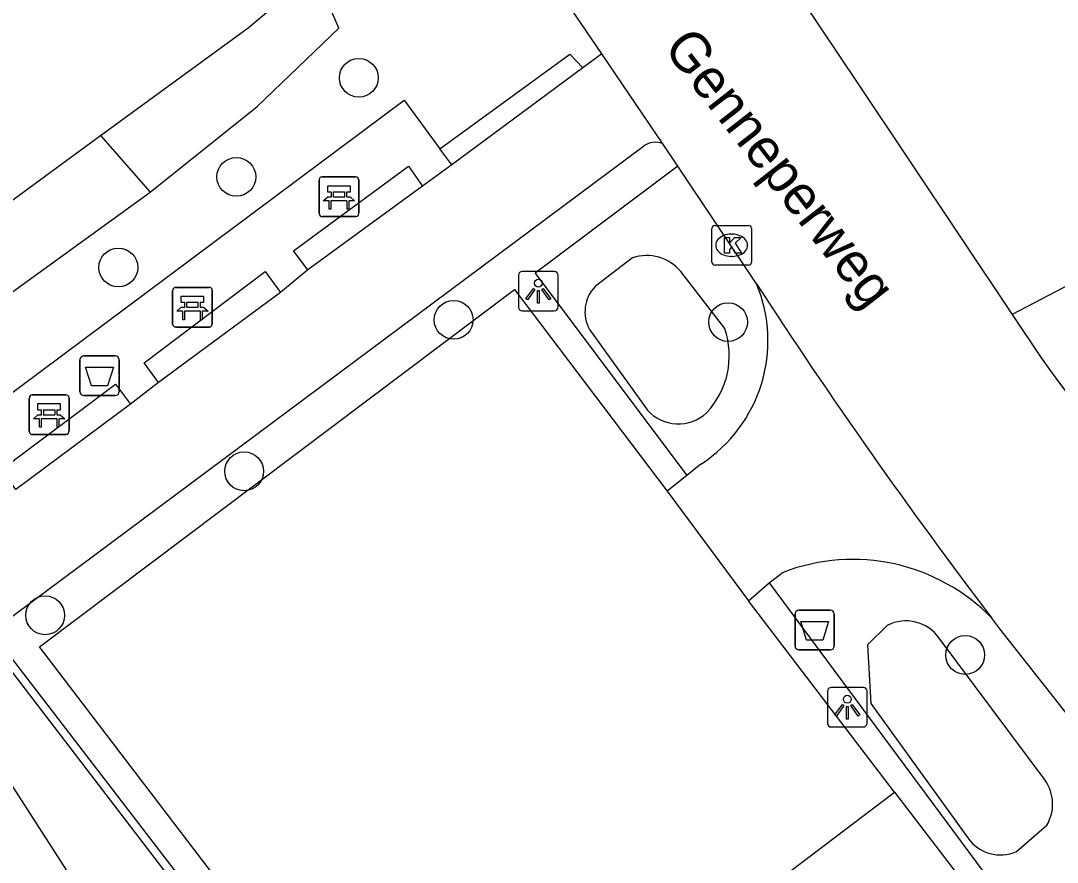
# Model space of a CAD drawing. Extents: x 160203 to 161526, y 379529 to 381797.
# Drawn here: x 160758.29 to 160784.41, y 381511.28 to 381532.5 of the extents above; entities that cross this region are included whole.
import ezdxf

# ---------------------------------------------------------------- set-up
doc = ezdxf.new("R2010")
doc.units = 0
for name, color, linetype in [('IMGEO_Afvalbak', 7, 'Continuous'), ('IMGEO_Bank', 7, 'Continuous'), ('IMGEO_Boom', 7, 'Continuous'), ('IMGEO_Groenvoorziening', 7, 'Continuous'), ('IMGEO_Haag', 7, 'Continuous'), ('IMGEO_Kolk', 7, 'Continuous'), ('IMGEO_Lichtpunt', 7, 'Continuous'), ('IMGEO_Oever', 7, 'Continuous'), ('IMGEO_Openbare_ruimte_label', 7, 'Continuous'), ('IMGEO_Parkeervlak_halfverhard', 7, 'Continuous'), ('IMGEO_Rijbaan_lokaal_gesloten', 7, 'Continuous'), ('IMGEO_Rijbaan_lokaal_open', 7, 'Continuous'), ('IMGEO_Voetpad_open', 7, 'Continuous'), ('IMGEO_Waterloop', 7, 'Continuous')]:
    doc.layers.add(name, color=color, linetype=linetype)

msp = doc.modelspace()

# ---------------------------------------------------------------- linework, layer by layer
at = {"layer": 'IMGEO_Afvalbak'}
for p, q in [((160759.78, 381523.147), (160759.78, 381523.947)), ((160759.78, 381523.947), (160759.78, 381523.147)), ((160759.88, 381524.047), (160760.67, 381524.047)), ((160760.67, 381524.047), (160759.88, 381524.047)), ((160760.77, 381523.947), (160760.77, 381523.147)), ((160760.77, 381523.147), (160760.77, 381523.947)), ((160760.67, 381523.047), (160759.88, 381523.047)), ((160759.88, 381523.047), (160760.67, 381523.047)), ((160777.798, 381516.733), (160777.798, 381517.533)), ((160777.798, 381517.533), (160777.798, 381516.733)), ((160777.898, 381517.633), (160778.688, 381517.633)), ((160778.688, 381517.633), (160777.898, 381517.633)), ((160778.788, 381517.533), (160778.788, 381516.733)), ((160778.788, 381516.733), (160778.788, 381517.533)), ((160778.688, 381516.633), (160777.898, 381516.633)), ((160777.898, 381516.633), (160778.688, 381516.633))]:
    msp.add_line(p, q, dxfattribs=at)
for points in [[(160759.923, 381523.761), (160760.627, 381523.761), (160760.478, 381523.291), (160760.072, 381523.291), (160759.923, 381523.761)], [(160777.941, 381517.347), (160778.645, 381517.347), (160778.496, 381516.877), (160778.09, 381516.877), (160777.941, 381517.347)]]:
    msp.add_lwpolyline(points, dxfattribs=at)
for centre, start, end in [((160759.88, 381523.947), 90, 180), ((160759.88, 381523.947), 90, 180), ((160760.67, 381523.947), 0, 90), ((160760.67, 381523.947), 360, 90), ((160759.88, 381523.147), 180, 270), ((160759.88, 381523.147), 180, 270), ((160760.67, 381523.147), 270, 0), ((160760.67, 381523.147), 270, 0), ((160777.898, 381517.533), 90, 180), ((160777.898, 381517.533), 90, 180), ((160778.688, 381517.533), 0, 90), ((160778.688, 381517.533), 360, 90), ((160777.898, 381516.733), 180, 270), ((160777.898, 381516.733), 180, 270), ((160778.688, 381516.733), 270, 0), ((160778.688, 381516.733), 270, 0)]:
    msp.add_arc(centre, 0.1, start, end, dxfattribs=at)
at = {"layer": 'IMGEO_Bank'}
for p, q in [((160765.806, 381527.634), (160765.806, 381528.475)), ((160765.806, 381528.475), (160765.806, 381527.634)), ((160765.881, 381528.559), (160766.722, 381528.559)), ((160766.722, 381528.559), (160765.881, 381528.559)), ((160766.806, 381528.484), (160766.806, 381527.643)), ((160766.806, 381527.643), (160766.806, 381528.484)), ((160766.115, 381528.065), (160766.115, 381528.171)), ((160766.159, 381528.171), (160766.159, 381528.065)), ((160766.447, 381528.177), (160766.165, 381528.177)), ((160766.453, 381528.065), (160766.453, 381528.171)), ((160766.497, 381528.171), (160766.497, 381528.065)), ((160766.503, 381527.957), (160766.11, 381527.957)), ((160766.165, 381528.059), (160766.447, 381528.059)), ((160766.731, 381527.559), (160765.89, 381527.559)), ((160765.89, 381527.559), (160766.731, 381527.559)), ((160762.19, 381525.775), (160763.031, 381525.775)), ((160763.031, 381525.775), (160762.19, 381525.775)), ((160762.115, 381524.85), (160762.115, 381525.691)), ((160762.115, 381525.691), (160762.115, 381524.85)), ((160763.115, 381525.7), (160763.115, 381524.859)), ((160763.115, 381524.859), (160763.115, 381525.7)), ((160762.424, 381525.281), (160762.424, 381525.387)), ((160762.468, 381525.387), (160762.468, 381525.281)), ((160762.756, 381525.393), (160762.474, 381525.393)), ((160762.474, 381525.275), (160762.756, 381525.275)), ((160762.762, 381525.281), (160762.762, 381525.387)), ((160762.806, 381525.387), (160762.806, 381525.281)), ((160762.812, 381525.173), (160762.419, 381525.173)), ((160763.04, 381524.775), (160762.199, 381524.775)), ((160762.199, 381524.775), (160763.04, 381524.775)), ((160758.504, 381522.139), (160758.504, 381522.98)), ((160758.504, 381522.98), (160758.504, 381522.139)), ((160758.579, 381523.064), (160759.42, 381523.064)), ((160759.42, 381523.064), (160758.579, 381523.064)), ((160759.504, 381522.989), (160759.504, 381522.148)), ((160759.504, 381522.148), (160759.504, 381522.989)), ((160758.813, 381522.57), (160758.813, 381522.676)), ((160758.857, 381522.676), (160758.857, 381522.57)), ((160759.145, 381522.682), (160758.863, 381522.682)), ((160759.151, 381522.57), (160759.151, 381522.676)), ((160759.195, 381522.676), (160759.195, 381522.57)), ((160759.201, 381522.462), (160758.808, 381522.462)), ((160758.863, 381522.564), (160759.145, 381522.564)), ((160759.429, 381522.064), (160758.588, 381522.064)), ((160758.588, 381522.064), (160759.429, 381522.064))]:
    msp.add_line(p, q, dxfattribs=at)
for points in [[(160766.109, 381528.177), (160766.023, 381528.177), (160766.023, 381528.338), (160766.586, 381528.338), (160766.586, 381528.177), (160766.503, 381528.177)], [(160766.053, 381527.957), (160765.911, 381527.957), (160766.023, 381528.059), (160766.109, 381528.059)], [(160766.103, 381527.95), (160766.103, 381527.743), (160766.06, 381527.743), (160766.06, 381527.95)], [(160766.503, 381528.059), (160766.586, 381528.059), (160766.698, 381527.957), (160766.559, 381527.957)], [(160766.553, 381527.95), (160766.553, 381527.743), (160766.509, 381527.743), (160766.509, 381527.95)], [(160762.418, 381525.393), (160762.332, 381525.393), (160762.332, 381525.554), (160762.895, 381525.554), (160762.895, 381525.393), (160762.812, 381525.393)], [(160762.362, 381525.173), (160762.22, 381525.173), (160762.332, 381525.275), (160762.418, 381525.275)], [(160762.812, 381525.275), (160762.895, 381525.275), (160763.007, 381525.173), (160762.868, 381525.173)], [(160762.412, 381525.166), (160762.412, 381524.959), (160762.369, 381524.959), (160762.369, 381525.166)], [(160762.862, 381525.166), (160762.862, 381524.959), (160762.818, 381524.959), (160762.818, 381525.166)], [(160758.807, 381522.682), (160758.721, 381522.682), (160758.721, 381522.843), (160759.284, 381522.843), (160759.284, 381522.682), (160759.201, 381522.682)], [(160758.751, 381522.462), (160758.609, 381522.462), (160758.721, 381522.564), (160758.807, 381522.564)], [(160758.801, 381522.455), (160758.801, 381522.248), (160758.758, 381522.248), (160758.758, 381522.455)], [(160759.201, 381522.564), (160759.284, 381522.564), (160759.396, 381522.462), (160759.257, 381522.462)], [(160759.251, 381522.455), (160759.251, 381522.248), (160759.207, 381522.248), (160759.207, 381522.455)]]:
    msp.add_lwpolyline(points, dxfattribs=at)
for centre, radius, start, end in [((160765.884, 381528.481), 0.0779, 92.4484, 184.2845), ((160765.884, 381528.481), 0.0779, 92.4484, 184.2845), ((160766.728, 381528.481), 0.0779, 2.4484, 94.2845), ((160766.728, 381528.481), 0.0779, 2.4484, 94.2845), ((160766.108, 381528.17), 0.00671, 2.8957, 87.1043), ((160766.165, 381528.17), 0.00671, 92.8957, 177.1043), ((160766.447, 381528.17), 0.00671, 2.8957, 87.1043), ((160766.504, 381528.17), 0.00671, 92.8957, 177.1043), ((160766.053, 381527.95), 0.00671, 2.8957, 87.1043), ((160766.11, 381527.95), 0.00671, 92.8957, 177.1043), ((160766.108, 381528.066), 0.00671, 272.8957, 357.1043), ((160766.165, 381528.066), 0.00671, 182.8957, 267.1043), ((160766.447, 381528.066), 0.00671, 272.8957, 357.1043), ((160766.504, 381528.066), 0.00671, 182.8957, 267.1043), ((160766.502, 381527.95), 0.00671, 2.8957, 87.1043), ((160766.559, 381527.95), 0.00671, 92.8957, 177.1043), ((160765.884, 381527.637), 0.0779, 182.4484, 274.2845), ((160765.884, 381527.637), 0.0779, 182.4484, 274.2845), ((160766.728, 381527.637), 0.0779, 272.4484, 4.2845), ((160766.728, 381527.637), 0.0779, 272.4484, 4.2845), ((160762.193, 381525.697), 0.0779, 92.4484, 184.2845), ((160762.193, 381525.697), 0.0779, 92.4484, 184.2845), ((160763.037, 381525.697), 0.0779, 2.4484, 94.2845), ((160763.037, 381525.697), 0.0779, 2.4484, 94.2845), ((160762.417, 381525.386), 0.00671, 2.8957, 87.1043), ((160762.417, 381525.282), 0.00671, 272.8957, 357.1043), ((160762.474, 381525.386), 0.00671, 92.8957, 177.1043), ((160762.474, 381525.282), 0.00671, 182.8957, 267.1043), ((160762.756, 381525.386), 0.00671, 2.8957, 87.1043), ((160762.756, 381525.282), 0.00671, 272.8957, 357.1043), ((160762.813, 381525.386), 0.00671, 92.8957, 177.1043), ((160762.813, 381525.282), 0.00671, 182.8957, 267.1043), ((160762.362, 381525.166), 0.00671, 2.8957, 87.1043), ((160762.419, 381525.166), 0.00671, 92.8957, 177.1043), ((160762.811, 381525.166), 0.00671, 2.8957, 87.1043), ((160762.868, 381525.166), 0.00671, 92.8957, 177.1043), ((160762.193, 381524.853), 0.0779, 182.4484, 274.2845), ((160762.193, 381524.853), 0.0779, 182.4484, 274.2845), ((160763.037, 381524.853), 0.0779, 272.4484, 4.2845), ((160763.037, 381524.853), 0.0779, 272.4484, 4.2845), ((160758.582, 381522.986), 0.0779, 92.4484, 184.2845), ((160758.582, 381522.986), 0.0779, 92.4484, 184.2845), ((160759.426, 381522.986), 0.0779, 2.4484, 94.2845), ((160759.426, 381522.986), 0.0779, 2.4484, 94.2845), ((160758.806, 381522.675), 0.00671, 2.8957, 87.1043), ((160758.863, 381522.675), 0.00671, 92.8957, 177.1043), ((160759.145, 381522.675), 0.00671, 2.8957, 87.1043), ((160759.202, 381522.675), 0.00671, 92.8957, 177.1043), ((160758.751, 381522.455), 0.00671, 2.8957, 87.1043), ((160758.808, 381522.455), 0.00671, 92.8957, 177.1043), ((160758.806, 381522.571), 0.00671, 272.8957, 357.1043), ((160758.863, 381522.571), 0.00671, 182.8957, 267.1043), ((160759.145, 381522.571), 0.00671, 272.8957, 357.1043), ((160759.202, 381522.571), 0.00671, 182.8957, 267.1043), ((160759.2, 381522.455), 0.00671, 2.8957, 87.1043), ((160759.257, 381522.455), 0.00671, 92.8957, 177.1043), ((160758.582, 381522.142), 0.0779, 182.4484, 274.2845), ((160758.582, 381522.142), 0.0779, 182.4484, 274.2845), ((160759.426, 381522.142), 0.0779, 272.4484, 4.2845), ((160759.426, 381522.142), 0.0779, 272.4484, 4.2845)]:
    msp.add_arc(centre, radius, start, end, dxfattribs=at)
at = {"layer": 'IMGEO_Boom'}
for centre in [(160766.806, 381531.059), (160763.72, 381528.56), (160760.747, 381526.276), (160769.196, 381524.955), (160776.112, 381524.899), (160763.917, 381521.136), (160758.903, 381517.506), (160782.087, 381516.505)]:
    msp.add_circle(centre, 0.489, dxfattribs=at)
at = {"layer": 'IMGEO_Groenvoorziening'}
for points in [[(160761.545, 381528.175), (160764.244, 381530.339), (160766.301, 381532.313), (160766.102, 381532.781), (160765.423, 381533.506)], [(160748.707, 381518.45), (160751.828, 381521.043), (160754.07, 381522.473), (160756.183, 381524.294), (160761.545, 381528.175)]]:
    msp.add_lwpolyline(points, dxfattribs=at)
at = {"layer": 'IMGEO_Haag'}
for points in [[(160768.851, 381529.264), (160772.126, 381531.655), (160772.455, 381531.312)], [(160774.849, 381528.832), (160771.25, 381526.13), (160775.076, 381521.03)], [(160777.151, 381518.322), (160782.542, 381511.048)], [(160755.271, 381515.391), (160755.672, 381514.811), (160757.992, 381516.503), (160773.641, 381496.114), (160778, 381491.284)], [(160780.301, 381513.047), (160782.089, 381510.714), (160782.542, 381511.048)]]:
    msp.add_lwpolyline(points, dxfattribs=at)
at = {"layer": 'IMGEO_Kolk'}
for p, q in [((160775.777, 381527.336), (160776.629, 381527.336)), ((160775.702, 381526.41), (160775.702, 381527.262)), ((160776.19, 381527.116), (160776.215, 381527.116)), ((160776.703, 381527.262), (160776.703, 381526.41)), ((160776.213, 381526.556), (160776.188, 381526.556)), ((160776.629, 381526.336), (160775.777, 381526.336))]:
    msp.add_line(p, q, dxfattribs=at)
for points in [[(160775.777, 381527.336), (160776.629, 381527.336)], [(160775.702, 381526.41), (160775.702, 381527.262)], [(160776.703, 381527.262), (160776.703, 381526.41)], [(160776.023, 381527.036), (160776.146, 381527.036), (160776.146, 381526.885), (160776.276, 381527.036), (160776.44, 381527.036), (160776.294, 381526.885), (160776.447, 381526.636), (160776.295, 381526.636), (160776.21, 381526.8), (160776.146, 381526.733), (160776.146, 381526.636), (160776.023, 381526.636), (160776.023, 381527.036)], [(160776.629, 381526.336), (160775.777, 381526.336)]]:
    msp.add_lwpolyline(points, dxfattribs=at)
for centre, start, end in [((160775.779, 381527.26), 91.552, 178.448), ((160775.779, 381527.26), 91.552, 178.448), ((160776.627, 381527.26), 1.552, 88.448), ((160776.627, 381527.26), 1.552, 88.448), ((160775.779, 381526.412), 181.552, 268.448), ((160775.779, 381526.412), 181.552, 268.448), ((160776.627, 381526.412), 271.552, 358.448), ((160776.627, 381526.412), 271.552, 358.448)]:
    msp.add_arc(centre, 0.0765, start, end, dxfattribs=at)
for centre, major_axis, ratio, start_param, end_param in [((160776.189, 381526.836), (-0.387, 0.002), 0.722429, 4.712389, 7.853982), ((160776.214, 381526.836), (-0.39, 0.002), 0.717154, 1.570796, 4.712389)]:
    msp.add_ellipse(centre, major_axis=major_axis, ratio=ratio, start_param=start_param, end_param=end_param, dxfattribs=at)
at = {"layer": 'IMGEO_Lichtpunt'}
for p, q in [((160770.831, 381526.083), (160770.831, 381525.276)), ((160770.831, 381526.083), (160770.831, 381525.276)), ((160771.733, 381526.178), (160770.925, 381526.178)), ((160771.733, 381526.178), (160770.925, 381526.178)), ((160771.827, 381525.276), (160771.827, 381526.083)), ((160771.827, 381525.276), (160771.827, 381526.083)), ((160770.925, 381525.182), (160771.733, 381525.182)), ((160770.925, 381525.182), (160771.733, 381525.182)), ((160778.618, 381515.591), (160778.618, 381514.784)), ((160778.618, 381515.591), (160778.618, 381514.784)), ((160779.52, 381515.686), (160778.712, 381515.686)), ((160779.52, 381515.686), (160778.712, 381515.686)), ((160779.614, 381514.784), (160779.614, 381515.591)), ((160779.614, 381514.784), (160779.614, 381515.591)), ((160778.712, 381514.69), (160779.52, 381514.69)), ((160778.712, 381514.69), (160779.52, 381514.69))]:
    msp.add_line(p, q, dxfattribs=at)
for points in [[(160771.205, 381525.747), (160771.244, 381525.719), (160771.056, 381525.457), (160771.018, 381525.484), (160771.205, 381525.747)], [(160771.307, 381525.699), (160771.354, 381525.699), (160771.354, 381525.377), (160771.307, 381525.377), (160771.307, 381525.699)], [(160771.417, 381525.719), (160771.455, 381525.746), (160771.642, 381525.484), (160771.603, 381525.456), (160771.417, 381525.719)], [(160778.992, 381515.255), (160779.031, 381515.227), (160778.843, 381514.965), (160778.805, 381514.992), (160778.992, 381515.255)], [(160779.094, 381515.207), (160779.141, 381515.207), (160779.141, 381514.885), (160779.094, 381514.885), (160779.094, 381515.207)], [(160779.204, 381515.227), (160779.242, 381515.254), (160779.429, 381514.992), (160779.39, 381514.964), (160779.204, 381515.227)]]:
    msp.add_lwpolyline(points, dxfattribs=at)
for centre in [(160771.33, 381525.881), (160779.117, 381515.389)]:
    msp.add_circle(centre, 0.0994, dxfattribs=at)
for centre, start, end in [((160770.925, 381526.083), 90, 180), ((160770.925, 381526.083), 90, 180), ((160771.733, 381526.083), 0, 90), ((160771.733, 381526.083), 0, 90), ((160770.925, 381525.276), 180, 270), ((160770.925, 381525.276), 180, 270), ((160771.733, 381525.276), 270, 0), ((160771.733, 381525.276), 270, 360), ((160778.712, 381515.591), 90, 180), ((160778.712, 381515.591), 90, 180), ((160779.52, 381515.591), 0, 90), ((160779.52, 381515.591), 0, 90), ((160778.712, 381514.784), 180, 270), ((160778.712, 381514.784), 180, 270), ((160779.52, 381514.784), 270, 0), ((160779.52, 381514.784), 270, 360)]:
    msp.add_arc(centre, 0.0946, start, end, dxfattribs=at)
at = {"layer": 'IMGEO_Oever'}
msp.add_lwpolyline([(160760.295, 381529.601), (160761.545, 381528.175)], dxfattribs=at)
at = {"layer": 'IMGEO_Parkeervlak_halfverhard'}
for points in [[(160768.431, 381504.038), (160758.759, 381516.713), (160770.727, 381525.717), (160774.574, 381520.639)], [(160780.301, 381513.047), (160776.629, 381517.874)], [(160768.431, 381504.038), (160780.301, 381513.047)]]:
    msp.add_lwpolyline(points, dxfattribs=at)
at = {"layer": 'IMGEO_Rijbaan_lokaal_gesloten'}
for points in [[(160775.687, 381536.434), (160779.362, 381530.937), (160783.272, 381525.087)], [(160772.927, 381531.663), (160771.474, 381533.804), (160771.423, 381533.87), (160771.371, 381533.937)], [(160774.467, 381529.394), (160772.927, 381531.663)], [(160774.849, 381528.832), (160774.467, 381529.394)], [(160776.828, 381525.864), (160774.849, 381528.832)], [(160783.272, 381525.087), (160783.985, 381524.02)], [(160790.107, 381508.498), (160789.646, 381509.04), (160785.025, 381514.538), (160782.962, 381517.164), (160782.759, 381517.43)]]:
    msp.add_lwpolyline(points, dxfattribs=at)
for centre, radius, start, end in [((160891.535, 381600.227), 136.702, 212.9546, 217.2771), ((160878.521, 381592.122), 116.511, 215.76827, 221.86749)]:
    msp.add_arc(centre, radius, start, end, dxfattribs=at)
at = {"layer": 'IMGEO_Rijbaan_lokaal_open'}
for points in [[(160772.927, 381531.663), (160772.455, 381531.312)], [(160772.455, 381531.312), (160769.154, 381528.862)], [(160773.978, 381529.329), (160755.271, 381515.391)], [(160769.154, 381528.862), (160768.415, 381528.327)], [(160768.415, 381528.327), (160765.518, 381526.214)], [(160788.18, 381527.659), (160783.272, 381525.087)], [(160765.518, 381526.214), (160764.835, 381525.649)], [(160764.835, 381525.649), (160761.76, 381523.378)], [(160761.76, 381523.378), (160761.051, 381522.83)], [(160761.051, 381522.83), (160758.161, 381520.68)], [(160775.425, 381521.316), (160775.076, 381521.03)], [(160775.076, 381521.03), (160774.574, 381520.639)], [(160774.574, 381520.639), (160776.629, 381517.874)], [(160777.151, 381518.322), (160777.502, 381518.589)], [(160776.629, 381517.874), (160777.151, 381518.322)]]:
    msp.add_lwpolyline(points, dxfattribs=at)
for centre, radius, start, end in [((160774.279, 381528.938), 0.494, 67.5893, 127.5539), ((160773.399, 381524.432), 3.717, 303.0418, 22.6696), ((160779.254, 381514.035), 4.879, 44.0887, 111.0453)]:
    msp.add_arc(centre, radius, start, end, dxfattribs=at)
at = {"layer": 'IMGEO_Voetpad_open'}
for points in [[(160756.955, 381520.513), (160756.096, 381521.654), (160767.949, 381530.494), (160768.851, 381529.264)], [(160769.154, 381528.862), (160768.851, 381529.264)], [(160765.518, 381526.214), (160765.158, 381526.699), (160768.057, 381528.829), (160768.415, 381528.327)], [(160761.76, 381523.378), (160761.395, 381523.873), (160764.448, 381526.175), (160764.835, 381525.649)], [(160758.161, 381520.68), (160757.798, 381521.176), (160760.673, 381523.336), (160761.051, 381522.83)]]:
    msp.add_lwpolyline(points, dxfattribs=at)
at = {"layer": 'IMGEO_Waterloop'}
for points in [[(160760.295, 381529.601), (160764.016, 381532.322), (160765.423, 381533.506)], [(160715.665, 381462.765), (160715.791, 381462.958), (160719.639, 381470.187), (160722.825, 381477.73), (160722.904, 381477.943), (160725.755, 381484.06), (160734.409, 381500), (160735.954, 381504.59), (160738.191, 381508.782), (160740.713, 381511.836), (160747.596, 381518.896), (160757.483, 381527.544), (160760.295, 381529.601)], [(160773.703, 381526.516), (160772.768, 381525.802)], [(160776.028, 381524.737), (160774.923, 381526.171)], [(160772.621, 381524.709), (160774.081, 381522.679)], [(160780.123, 381517.249), (160779.621, 381516.76), (160779.712, 381515.283), (160782.156, 381511.89)], [(160784.102, 381513.348), (160781.434, 381516.929)], [(160775.459, 381493.355), (160770.376, 381500), (160757.997, 381516.181), (160756.738, 381515.266), (160763.091, 381505.387), (160767.626, 381500), (160769.974, 381497.211), (160774.413, 381492.316), (160775.459, 381493.355)], [(160783.379, 381511.548), (160784.147, 381512.216)]]:
    msp.add_lwpolyline(points, dxfattribs=at)
for centre, radius, start, end in [((160774.065, 381525.467), 1.109, 39.3589, 109.0606), ((160773.431, 381525.156), 0.926, 135.7794, 208.9008), ((160774.027, 381524.054), 2.114, 316.8712, 18.8363), ((160774.86, 381523.386), 1.053, 222.2274, 312.3894), ((160780.595, 381516.339), 1.025, 35.1261, 117.4399), ((160783.227, 381512.746), 1.062, 330.048, 34.505), ((160782.976, 381512.463), 1, 214.9572, 293.7965)]:
    msp.add_arc(centre, radius, start, end, dxfattribs=at)

# ---------------------------------------------------------------- texts
at = {"layer": 'IMGEO_Openbare_ruimte_label'}
msp.add_text('Genneperweg', height=1, rotation=307.9353, dxfattribs=at).set_placement((160774.457, 381531.809))

doc.saveas('drawing.dxf')
